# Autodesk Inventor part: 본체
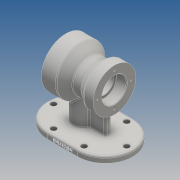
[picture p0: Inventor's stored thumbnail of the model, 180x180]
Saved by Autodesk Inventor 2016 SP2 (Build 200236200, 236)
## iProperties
Created: 2020-01
Part Number: 본체
Material: 알루미늄 6061
Document SubType Name: Modeling
Designer: EZ
Density: 2.7 g/cm^3
Appearance: 기본값
Mass: 930.253 g
Surface Area: 651.434 cm^2
Volume: 344.538 cm^3
Author: EZ
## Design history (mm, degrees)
sketch "스케치1"
  geometry: L1 (0, 0)-(-80, 0); L2 (0, 40)-(0, 26); L3 (0, 26)-(-19.7, 26); L4 (-20, 25.7)-(-20, 16); L5 (-20, 16)-(-63, 16); L6 (-63, 16)-(-63, 19.7); L7 (-63.3, 20)-(-80, 20); L8 (-80, 20)-(-80, 35); L9 (-80, 35)-(-64, 35); L10 (-64, 35)-(-53.289, 27.5); L11 (-53.289, 27.5)-(-38.897, 27.5); L12 (-38.897, 27.5)-(-24, 40); L13 (-24, 40)-(0, 40); A1 r 0.3 centre (-19.7, 25.7) between (-19.7, 26) and (-20, 25.7); A2 r 0.3 centre (-63.3, 19.7) between (-63, 19.7) and (-63.3, 20)
  constraints: 27 end point, 7 perpendicular, 4 point on circle, 4 tangent, 2 centre point, 2 parallel, 2 point on line, 1 equal radius, 1 horizontal, 1 vertical
  dimensions: "d0" = 80 distance of L1.start L1.end; "d2" = 80 diameter of L13 L1; "d3" = 52 diameter of L3 L1; "d4" = 20 distance between parallel lines of L4 L2; "d5" = 17 distance between parallel lines of L8 L6; "d6" = 24 distance of L12.end L2.start; "d7" = 16 distance of L8.end L9.end; "d8" = 32 diameter of L5 L1; "d9" = 40 diameter of L7 L1; "d10" = 70 diameter of L9 L1; "d11" = 55 diameter of L11 L1; "d12" = 0.3 radius of A1; "d13" = 40 deg angle of L12 L11; "d14" = 35 deg angle of L10 L11
revolve "회전1" sketch "스케치1" stored, may be unused: angle "d15" = 90 deg
fillet "모깎기1" dims "d16" = 3
chamfer "모따기1" distance "d17" = 1; stored, may be unused: second distance "d18" = 2, angle "d19" = 45 deg
node "작업 평면1"
sketch "스케치2"
  geometry: L1 (15, 0)-(65, 0); L2 (15, -45)-(65, -45); L3 (65, 45)-(15, 45); L4 (0, 40)-(0, -40) reference; L5 (0, 0)-(145.446, 0); A1 r 45 centre (15, 0) between (15, 45) and (15, -45); A2 r 45 centre (65, 0) between (65, -45) and (65, 45); 1 further point
  constraints: 10 end point, 4 point on circle, 4 tangent, 2 centre point, 2 horizontal, 1 midpoint, 1 parallel, 1 other
  dimensions: "d21" = 50 distance of L1.start L1.end; "d23" = 45 radius of A1; "d25" = 30 distance edge to line of A1 L4
extrude "돌출1" join sketch "스케치2" distance "d26" = 10; taper "d27" = 0 deg
sketch "스케치3"
  geometry: L1 (65, 45)-(15, 45) reference; L2 (15, -45)-(65, -45) reference; L3 (65, 45)-(15, 45) reference; L4 (65, -35)-(15, -35); L5 (15, 35)-(65, 35); A1 r 45 centre (65, 0) between (65, -45) and (65, 45) reference; A2 r 45 centre (15, 0) between (15, 45) and (15, -45) reference; A3 r 45 centre (15, 0) between (15, 45) and (15, -45) reference; A4 r 45 centre (65, 0) between (65, -45) and (65, 45) reference; A5 r 35 centre (15, 0) between (15, 35) and (15, -35); A6 r 35 centre (65, 0) between (65, -35) and (65, 35); 6 further points
  constraints: 6 point on circle, 4 coincident, 4 end point, 2 centre point, 3 other
  dimensions: "d29" = 10 distance between parallel lines of L2 L4
hole "구멍1" sketch "스케치3" at (15, -35), (65, -35), (100, 0), (65, 35), (15, 35), (-20, 0) diameter "d30" = 9; stored, may be unused: countersink angle "d34" = 90 deg, drill point angle "d36" = 118 deg; dims "d31" = 6, "d32" = 4, "d33" = 2, "d35" = 8
sketch "스케치4"
  geometry: L1 (-30, 0)-(28, 0); L2 (43.199, 5)-(70, 5); L3 (70, 5)-(70, -5); L4 (70, -5)-(43.199, -5); L5 (80, 35)-(80, -35) reference; A1 r 45 centre (15, 0) between (15, 45) and (15, -45) reference; A2 r 16 centre (28, 0) between (43.199, 5) and (43.199, -5)
  constraints: 8 end point, 3 point on circle, 2 horizontal, 2 perpendicular, 1 centre point, 1 coincident, 1 other
  dimensions: "d38" = 58 distance of L1.start L1.end; "d39" = 32 diameter of A2; "d41" = 10 distance of L2.end L3.end; "d77" = 10 distance between parallel lines of L5 L3
extrude "돌출2" join sketch "스케치4" stored distance "d42" = 10; taper "d43" = 0 deg
fillet "모깎기4" dims "d46" = 3
sketch "스케치5" dims "d47" = 66
  geometry: 3 further points
  constraints: 2 horizontal alignment, 1 coincident, 2 other
hole "구멍2" sketch "스케치5" at (33, 0) diameter "d48" = 3.242; stored, may be unused: countersink angle "d52" = 90 deg, drill point angle "d54" = 118 deg; dims "d49" = 9, "d50" = 4, "d51" = 2, "d53" = 11
sketch "스케치6" dims "d58" = 55
  geometry: 3 further points
  constraints: 2 horizontal alignment, 1 coincident, 2 other
hole "구멍3" sketch "스케치6" at (-27.5, 0) diameter "d59" = 3.242; stored, may be unused: countersink angle "d63" = 90 deg, drill point angle "d65" = 118 deg; dims "d60" = 9, "d61" = 4, "d62" = 2, "d64" = 11
sketch "스케치7"
  geometry: L1 (95, 0)-(50, 0) reference; L2 (-45, 0)-(-45, 7) reference; 2 further points
  constraints: 1 other
  dimensions: "d69" = 4 distance from line of L1 point (25, 4); "d70" = 70 distance from line of L2 point (25, 4)
feature "엠보싱1" sketch "스케치7" dims "d0" = 80, "d2" = 80, "d3" = 52, "d4" = 20, "d5" = 17, "d6" = 24, "d7" = 16, "d8" = 32, "d9" = 40, "d10" = 70, "d11" = 55, "d12" = 0.3, "d13" = 40 deg, "d14" = 35 deg, "d71" = 0.5, "d72" = 0
fillet "모깎기6" dims "d74" = 3
fillet "모깎기7" dims "d75" = 3
fillet "모깎기8" dims "d76" = 3
node "솔리드1"
pattern_circular "원형 패턴1" dims angle "d56" = 360 deg
pattern_circular "원형 패턴2" dims angle "d67" = 360 deg
node "투영된 루프1"
